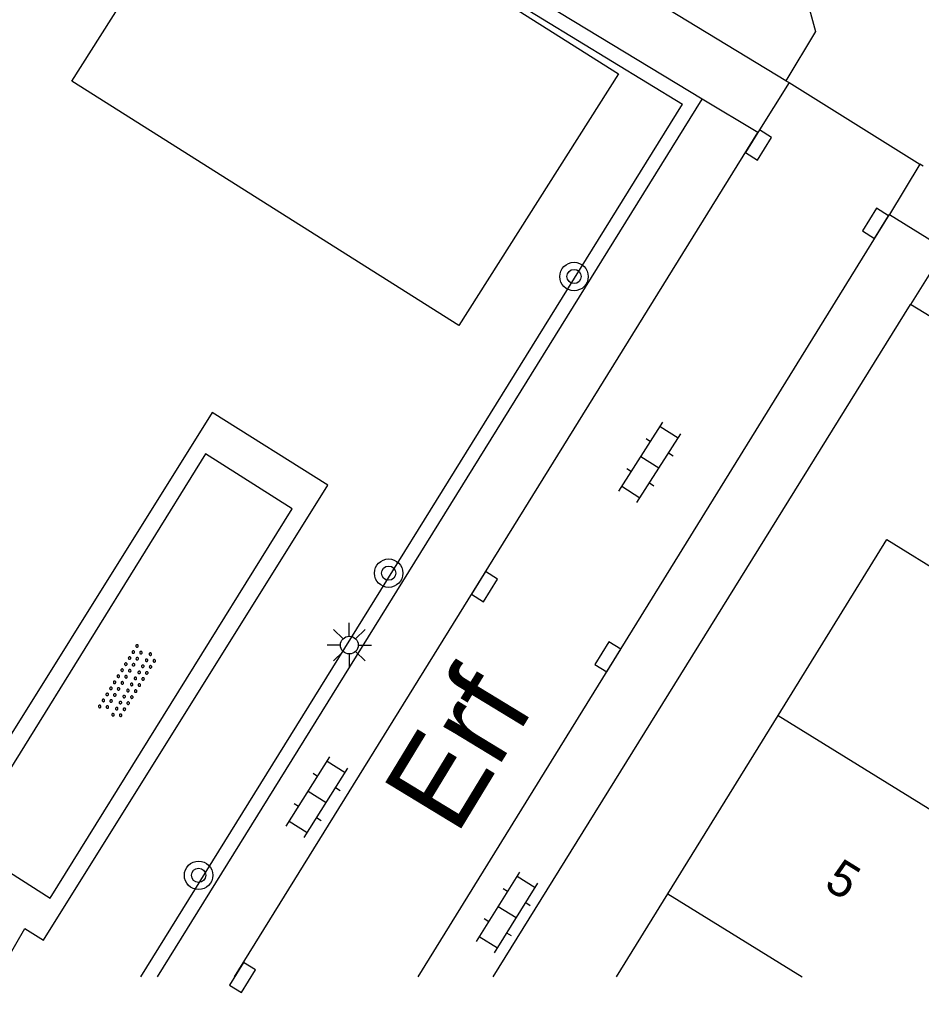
# Model space of a CAD drawing. Extents: x 136000 to 141014, y 402000 to 403500.
# Drawn here: x 137958.33 to 137983.69, y 401999.56 to 402026.92 of the extents above; entities that cross this region are included whole.
import ezdxf

# ---------------------------------------------------------------- set-up
doc = ezdxf.new("R2010")
doc.units = 0
for name, color, linetype in [('gg-anno-huisnummerreeks BGT', 7, 'Continuous'), ('gg-anno-openbare ruimte label', 7, 'Continuous'), ('gg-bbg-hoofdgebouw', 7, 'Continuous'), ('gg-bbg-tussenscheiding', 7, 'Continuous'), ('gg-knt-onverhard', 7, 'Continuous'), ('gg-knt-verharding', 7, 'Continuous'), ('gt-grn-groengrens', 7, 'Continuous'), ('gt-symb-boom', 7, 'Continuous'), ('gt-symb-klinker verharding', 7, 'Continuous'), ('gt-symb-kolk', 7, 'Continuous'), ('gt-symb-lichtmast', 7, 'Continuous'), ('gt-symb-overige verharding', 7, 'Continuous')]:
    doc.layers.add(name, color=color, linetype=linetype)

# ---------------------------------------------------------------- blocks, each defined once
blk = doc.blocks.new('gt0-KOLK')
at = {"layer": 'gt-symb-kolk'}
blk.add_lwpolyline([(0, 0), (0.375, 0), (0.375, 0.4), (-0.375, 0.4), (-0.375, 0), (0, 0)], dxfattribs=at)
blk = doc.blocks.new('gt0-KL1')
at = {"layer": 'gt-symb-klinker verharding'}
for p, q in [((-1.15, 0.3), (1.15, 0.3)), ((-1, -0.3), (-1, 0.3)), ((-0.5, 0.3), (-0.5, 0.45)), ((0, -0.3), (0, 0.3)), ((0.5, 0.3), (0.5, 0.45)), ((1, -0.3), (1, 0.3)), ((-1.15, -0.3), (1.15, -0.3)), ((-0.5, -0.45), (-0.5, -0.3)), ((0.5, -0.45), (0.5, -0.3))]:
    blk.add_line(p, q, dxfattribs=at)
blk = doc.blocks.new('gt0-OVH')
at = {"layer": 'gt-symb-overige verharding'}
for points in [[(-0.972, 0.298), (-0.967, 0.308), (-0.965, 0.319), (-0.966, 0.33), (-0.971, 0.34), (-0.978, 0.348), (-0.988, 0.353), (-0.999, 0.355), (-1.01, 0.354), (-1.02, 0.349), (-1.028, 0.342), (-1.033, 0.332), (-1.035, 0.321), (-1.034, 0.31), (-1.029, 0.3), (-1.022, 0.292), (-1.012, 0.287), (-1.001, 0.285), (-0.99, 0.286), (-0.98, 0.291)], [(-0.772, 0.298), (-0.767, 0.308), (-0.765, 0.319), (-0.766, 0.33), (-0.771, 0.34), (-0.778, 0.348), (-0.788, 0.353), (-0.799, 0.355), (-0.81, 0.354), (-0.82, 0.349), (-0.828, 0.342), (-0.833, 0.332), (-0.835, 0.321), (-0.834, 0.31), (-0.829, 0.3), (-0.822, 0.292), (-0.812, 0.287), (-0.801, 0.285), (-0.79, 0.286), (-0.78, 0.291)], [(-0.572, 0.298), (-0.567, 0.308), (-0.565, 0.319), (-0.566, 0.33), (-0.571, 0.34), (-0.578, 0.348), (-0.588, 0.353), (-0.599, 0.355), (-0.61, 0.354), (-0.62, 0.349), (-0.628, 0.342), (-0.633, 0.332), (-0.635, 0.321), (-0.634, 0.31), (-0.629, 0.3), (-0.622, 0.292), (-0.612, 0.287), (-0.601, 0.285), (-0.59, 0.286), (-0.58, 0.291)], [(-0.372, 0.298), (-0.367, 0.308), (-0.365, 0.319), (-0.366, 0.33), (-0.371, 0.34), (-0.378, 0.348), (-0.388, 0.353), (-0.399, 0.355), (-0.41, 0.354), (-0.42, 0.349), (-0.428, 0.342), (-0.433, 0.332), (-0.435, 0.321), (-0.434, 0.31), (-0.429, 0.3), (-0.422, 0.292), (-0.412, 0.287), (-0.401, 0.285), (-0.39, 0.286), (-0.38, 0.291)], [(-0.172, 0.298), (-0.167, 0.308), (-0.165, 0.319), (-0.166, 0.33), (-0.171, 0.34), (-0.178, 0.348), (-0.188, 0.353), (-0.199, 0.355), (-0.21, 0.354), (-0.22, 0.349), (-0.228, 0.342), (-0.233, 0.332), (-0.235, 0.321), (-0.234, 0.31), (-0.229, 0.3), (-0.222, 0.292), (-0.212, 0.287), (-0.201, 0.285), (-0.19, 0.286), (-0.18, 0.291)], [(0.028, 0.298), (0.033, 0.308), (0.035, 0.319), (0.034, 0.33), (0.029, 0.34), (0.022, 0.348), (0.012, 0.353), (0.001, 0.355), (-0.01, 0.354), (-0.02, 0.349), (-0.028, 0.342), (-0.033, 0.332), (-0.035, 0.321), (-0.034, 0.31), (-0.029, 0.3), (-0.022, 0.292), (-0.012, 0.287), (-0.001, 0.285), (0.01, 0.286), (0.02, 0.291)], [(0.228, 0.298), (0.233, 0.308), (0.235, 0.319), (0.234, 0.33), (0.229, 0.34), (0.222, 0.348), (0.212, 0.353), (0.201, 0.355), (0.19, 0.354), (0.18, 0.349), (0.172, 0.342), (0.167, 0.332), (0.165, 0.321), (0.166, 0.31), (0.171, 0.3), (0.178, 0.292), (0.188, 0.287), (0.199, 0.285), (0.21, 0.286), (0.22, 0.291)], [(0.428, 0.298), (0.433, 0.308), (0.435, 0.319), (0.434, 0.33), (0.429, 0.34), (0.422, 0.348), (0.412, 0.353), (0.401, 0.355), (0.39, 0.354), (0.38, 0.349), (0.372, 0.342), (0.367, 0.332), (0.365, 0.321), (0.366, 0.31), (0.371, 0.3), (0.378, 0.292), (0.388, 0.287), (0.399, 0.285), (0.41, 0.286), (0.42, 0.291)], [(0.628, 0.298), (0.633, 0.308), (0.635, 0.319), (0.634, 0.33), (0.629, 0.34), (0.622, 0.348), (0.612, 0.353), (0.601, 0.355), (0.59, 0.354), (0.58, 0.349), (0.572, 0.342), (0.567, 0.332), (0.565, 0.321), (0.566, 0.31), (0.571, 0.3), (0.578, 0.292), (0.588, 0.287), (0.599, 0.285), (0.61, 0.286), (0.62, 0.291)], [(0.828, 0.298), (0.833, 0.308), (0.835, 0.319), (0.834, 0.33), (0.829, 0.34), (0.822, 0.348), (0.812, 0.353), (0.801, 0.355), (0.79, 0.354), (0.78, 0.349), (0.772, 0.342), (0.767, 0.332), (0.765, 0.321), (0.766, 0.31), (0.771, 0.3), (0.778, 0.292), (0.788, 0.287), (0.799, 0.285), (0.81, 0.286), (0.82, 0.291)], [(1.028, 0.298), (1.033, 0.308), (1.035, 0.319), (1.034, 0.33), (1.029, 0.34), (1.022, 0.348), (1.012, 0.353), (1.001, 0.355), (0.99, 0.354), (0.98, 0.349), (0.972, 0.342), (0.967, 0.332), (0.965, 0.321), (0.966, 0.31), (0.971, 0.3), (0.978, 0.292), (0.988, 0.287), (0.999, 0.285), (1.01, 0.286), (1.02, 0.291)], [(-0.872, 0.106), (-0.867, 0.116), (-0.865, 0.126), (-0.866, 0.137), (-0.871, 0.147), (-0.878, 0.156), (-0.888, 0.161), (-0.899, 0.163), (-0.91, 0.162), (-0.92, 0.157), (-0.928, 0.15), (-0.933, 0.14), (-0.935, 0.129), (-0.934, 0.118), (-0.929, 0.108), (-0.922, 0.1), (-0.912, 0.095), (-0.901, 0.092), (-0.89, 0.094), (-0.88, 0.098)], [(-0.672, 0.106), (-0.667, 0.116), (-0.665, 0.126), (-0.666, 0.137), (-0.671, 0.147), (-0.678, 0.156), (-0.688, 0.161), (-0.699, 0.163), (-0.71, 0.162), (-0.72, 0.157), (-0.728, 0.15), (-0.733, 0.14), (-0.735, 0.129), (-0.734, 0.118), (-0.729, 0.108), (-0.722, 0.1), (-0.712, 0.095), (-0.701, 0.092), (-0.69, 0.094), (-0.68, 0.098)], [(-0.472, 0.106), (-0.467, 0.116), (-0.465, 0.126), (-0.466, 0.137), (-0.471, 0.147), (-0.478, 0.156), (-0.488, 0.161), (-0.499, 0.163), (-0.51, 0.162), (-0.52, 0.157), (-0.528, 0.15), (-0.533, 0.14), (-0.535, 0.129), (-0.534, 0.118), (-0.529, 0.108), (-0.522, 0.1), (-0.512, 0.095), (-0.501, 0.092), (-0.49, 0.094), (-0.48, 0.098)], [(-0.272, 0.106), (-0.267, 0.116), (-0.265, 0.126), (-0.266, 0.137), (-0.271, 0.147), (-0.278, 0.156), (-0.288, 0.161), (-0.299, 0.163), (-0.31, 0.162), (-0.32, 0.157), (-0.328, 0.15), (-0.333, 0.14), (-0.335, 0.129), (-0.334, 0.118), (-0.329, 0.108), (-0.322, 0.1), (-0.312, 0.095), (-0.301, 0.092), (-0.29, 0.094), (-0.28, 0.098)], [(-0.072, 0.106), (-0.067, 0.116), (-0.065, 0.126), (-0.066, 0.137), (-0.071, 0.147), (-0.078, 0.156), (-0.088, 0.161), (-0.099, 0.163), (-0.11, 0.162), (-0.12, 0.157), (-0.128, 0.15), (-0.133, 0.14), (-0.135, 0.129), (-0.134, 0.118), (-0.129, 0.108), (-0.122, 0.1), (-0.112, 0.095), (-0.101, 0.092), (-0.09, 0.094), (-0.08, 0.098)], [(0.128, 0.106), (0.133, 0.116), (0.135, 0.126), (0.134, 0.137), (0.129, 0.147), (0.122, 0.156), (0.112, 0.161), (0.101, 0.163), (0.09, 0.162), (0.08, 0.157), (0.072, 0.15), (0.067, 0.14), (0.065, 0.129), (0.066, 0.118), (0.071, 0.108), (0.078, 0.1), (0.088, 0.095), (0.099, 0.092), (0.11, 0.094), (0.12, 0.098)], [(0.328, 0.106), (0.333, 0.116), (0.335, 0.126), (0.334, 0.137), (0.329, 0.147), (0.322, 0.156), (0.312, 0.161), (0.301, 0.163), (0.29, 0.162), (0.28, 0.157), (0.272, 0.15), (0.267, 0.14), (0.265, 0.129), (0.266, 0.118), (0.271, 0.108), (0.278, 0.1), (0.288, 0.095), (0.299, 0.092), (0.31, 0.094), (0.32, 0.098)], [(0.528, 0.106), (0.533, 0.116), (0.535, 0.126), (0.534, 0.137), (0.529, 0.147), (0.522, 0.156), (0.512, 0.161), (0.501, 0.163), (0.49, 0.162), (0.48, 0.157), (0.472, 0.15), (0.467, 0.14), (0.465, 0.129), (0.466, 0.118), (0.471, 0.108), (0.478, 0.1), (0.488, 0.095), (0.499, 0.092), (0.51, 0.094), (0.52, 0.098)], [(0.728, 0.106), (0.733, 0.116), (0.735, 0.126), (0.734, 0.137), (0.729, 0.147), (0.722, 0.156), (0.712, 0.161), (0.701, 0.163), (0.69, 0.162), (0.68, 0.157), (0.672, 0.15), (0.667, 0.14), (0.665, 0.129), (0.666, 0.118), (0.671, 0.108), (0.678, 0.1), (0.688, 0.095), (0.699, 0.092), (0.71, 0.094), (0.72, 0.098)], [(0.928, 0.106), (0.933, 0.116), (0.935, 0.126), (0.934, 0.137), (0.929, 0.147), (0.922, 0.156), (0.912, 0.161), (0.901, 0.163), (0.89, 0.162), (0.88, 0.157), (0.872, 0.15), (0.867, 0.14), (0.865, 0.129), (0.866, 0.118), (0.871, 0.108), (0.878, 0.1), (0.888, 0.095), (0.899, 0.092), (0.91, 0.094), (0.92, 0.098)], [(-0.972, -0.142), (-0.967, -0.132), (-0.965, -0.121), (-0.966, -0.11), (-0.971, -0.1), (-0.978, -0.092), (-0.988, -0.087), (-0.999, -0.085), (-1.01, -0.086), (-1.02, -0.091), (-1.028, -0.098), (-1.033, -0.108), (-1.035, -0.119), (-1.034, -0.13), (-1.029, -0.14), (-1.022, -0.148), (-1.012, -0.153), (-1.001, -0.155), (-0.99, -0.154), (-0.98, -0.149)], [(-0.772, -0.142), (-0.767, -0.132), (-0.765, -0.121), (-0.766, -0.11), (-0.771, -0.1), (-0.778, -0.092), (-0.788, -0.087), (-0.799, -0.085), (-0.81, -0.086), (-0.82, -0.091), (-0.828, -0.098), (-0.833, -0.108), (-0.835, -0.119), (-0.834, -0.13), (-0.829, -0.14), (-0.822, -0.148), (-0.812, -0.153), (-0.801, -0.155), (-0.79, -0.154), (-0.78, -0.149)], [(-0.572, -0.142), (-0.567, -0.132), (-0.565, -0.121), (-0.566, -0.11), (-0.571, -0.1), (-0.578, -0.092), (-0.588, -0.087), (-0.599, -0.085), (-0.61, -0.086), (-0.62, -0.091), (-0.628, -0.098), (-0.633, -0.108), (-0.635, -0.119), (-0.634, -0.13), (-0.629, -0.14), (-0.622, -0.148), (-0.612, -0.153), (-0.601, -0.155), (-0.59, -0.154), (-0.58, -0.149)], [(-0.372, -0.142), (-0.367, -0.132), (-0.365, -0.121), (-0.366, -0.11), (-0.371, -0.1), (-0.378, -0.092), (-0.388, -0.087), (-0.399, -0.085), (-0.41, -0.086), (-0.42, -0.091), (-0.428, -0.098), (-0.433, -0.108), (-0.435, -0.119), (-0.434, -0.13), (-0.429, -0.14), (-0.422, -0.148), (-0.412, -0.153), (-0.401, -0.155), (-0.39, -0.154), (-0.38, -0.149)], [(-0.172, -0.142), (-0.167, -0.132), (-0.165, -0.121), (-0.166, -0.11), (-0.171, -0.1), (-0.178, -0.092), (-0.188, -0.087), (-0.199, -0.085), (-0.21, -0.086), (-0.22, -0.091), (-0.228, -0.098), (-0.233, -0.108), (-0.235, -0.119), (-0.234, -0.13), (-0.229, -0.14), (-0.222, -0.148), (-0.212, -0.153), (-0.201, -0.155), (-0.19, -0.154), (-0.18, -0.149)], [(0.028, -0.142), (0.033, -0.132), (0.035, -0.121), (0.034, -0.11), (0.029, -0.1), (0.022, -0.092), (0.012, -0.087), (0.001, -0.085), (-0.01, -0.086), (-0.02, -0.091), (-0.028, -0.098), (-0.033, -0.108), (-0.035, -0.119), (-0.034, -0.13), (-0.029, -0.14), (-0.022, -0.148), (-0.012, -0.153), (-0.001, -0.155), (0.01, -0.154), (0.02, -0.149)], [(0.228, -0.142), (0.233, -0.132), (0.235, -0.121), (0.234, -0.11), (0.229, -0.1), (0.222, -0.092), (0.212, -0.087), (0.201, -0.085), (0.19, -0.086), (0.18, -0.091), (0.172, -0.098), (0.167, -0.108), (0.165, -0.119), (0.166, -0.13), (0.171, -0.14), (0.178, -0.148), (0.188, -0.153), (0.199, -0.155), (0.21, -0.154), (0.22, -0.149)], [(0.428, -0.142), (0.433, -0.132), (0.435, -0.121), (0.434, -0.11), (0.429, -0.1), (0.422, -0.092), (0.412, -0.087), (0.401, -0.085), (0.39, -0.086), (0.38, -0.091), (0.372, -0.098), (0.367, -0.108), (0.365, -0.119), (0.366, -0.13), (0.371, -0.14), (0.378, -0.148), (0.388, -0.153), (0.399, -0.155), (0.41, -0.154), (0.42, -0.149)], [(0.628, -0.142), (0.633, -0.132), (0.635, -0.121), (0.634, -0.11), (0.629, -0.1), (0.622, -0.092), (0.612, -0.087), (0.601, -0.085), (0.59, -0.086), (0.58, -0.091), (0.572, -0.098), (0.567, -0.108), (0.565, -0.119), (0.566, -0.13), (0.571, -0.14), (0.578, -0.148), (0.588, -0.153), (0.599, -0.155), (0.61, -0.154), (0.62, -0.149)], [(0.828, -0.142), (0.833, -0.132), (0.835, -0.121), (0.834, -0.11), (0.829, -0.1), (0.822, -0.092), (0.812, -0.087), (0.801, -0.085), (0.79, -0.086), (0.78, -0.091), (0.772, -0.098), (0.767, -0.108), (0.765, -0.119), (0.766, -0.13), (0.771, -0.14), (0.778, -0.148), (0.788, -0.153), (0.799, -0.155), (0.81, -0.154), (0.82, -0.149)], [(1.028, -0.142), (1.033, -0.132), (1.035, -0.121), (1.034, -0.11), (1.029, -0.1), (1.022, -0.092), (1.012, -0.087), (1.001, -0.085), (0.99, -0.086), (0.98, -0.091), (0.972, -0.098), (0.967, -0.108), (0.965, -0.119), (0.966, -0.13), (0.971, -0.14), (0.978, -0.148), (0.988, -0.153), (0.999, -0.155), (1.01, -0.154), (1.02, -0.149)], [(-0.872, -0.334), (-0.867, -0.324), (-0.865, -0.314), (-0.866, -0.303), (-0.871, -0.293), (-0.878, -0.284), (-0.888, -0.279), (-0.899, -0.277), (-0.91, -0.278), (-0.92, -0.283), (-0.928, -0.29), (-0.933, -0.3), (-0.935, -0.311), (-0.934, -0.322), (-0.929, -0.332), (-0.922, -0.34), (-0.912, -0.345), (-0.901, -0.348), (-0.89, -0.346), (-0.88, -0.342)], [(-0.672, -0.334), (-0.667, -0.324), (-0.665, -0.314), (-0.666, -0.303), (-0.671, -0.293), (-0.678, -0.284), (-0.688, -0.279), (-0.699, -0.277), (-0.71, -0.278), (-0.72, -0.283), (-0.728, -0.29), (-0.733, -0.3), (-0.735, -0.311), (-0.734, -0.322), (-0.729, -0.332), (-0.722, -0.34), (-0.712, -0.345), (-0.701, -0.348), (-0.69, -0.346), (-0.68, -0.342)], [(-0.472, -0.334), (-0.467, -0.324), (-0.465, -0.314), (-0.466, -0.303), (-0.471, -0.293), (-0.478, -0.284), (-0.488, -0.279), (-0.499, -0.277), (-0.51, -0.278), (-0.52, -0.283), (-0.528, -0.29), (-0.533, -0.3), (-0.535, -0.311), (-0.534, -0.322), (-0.529, -0.332), (-0.522, -0.34), (-0.512, -0.345), (-0.501, -0.348), (-0.49, -0.346), (-0.48, -0.342)], [(-0.272, -0.334), (-0.267, -0.324), (-0.265, -0.314), (-0.266, -0.303), (-0.271, -0.293), (-0.278, -0.284), (-0.288, -0.279), (-0.299, -0.277), (-0.31, -0.278), (-0.32, -0.283), (-0.328, -0.29), (-0.333, -0.3), (-0.335, -0.311), (-0.334, -0.322), (-0.329, -0.332), (-0.322, -0.34), (-0.312, -0.345), (-0.301, -0.348), (-0.29, -0.346), (-0.28, -0.342)], [(-0.072, -0.334), (-0.067, -0.324), (-0.065, -0.314), (-0.066, -0.303), (-0.071, -0.293), (-0.078, -0.284), (-0.088, -0.279), (-0.099, -0.277), (-0.11, -0.278), (-0.12, -0.283), (-0.128, -0.29), (-0.133, -0.3), (-0.135, -0.311), (-0.134, -0.322), (-0.129, -0.332), (-0.122, -0.34), (-0.112, -0.345), (-0.101, -0.348), (-0.09, -0.346), (-0.08, -0.342)], [(0.128, -0.334), (0.133, -0.324), (0.135, -0.314), (0.134, -0.303), (0.129, -0.293), (0.122, -0.284), (0.112, -0.279), (0.101, -0.277), (0.09, -0.278), (0.08, -0.283), (0.072, -0.29), (0.067, -0.3), (0.065, -0.311), (0.066, -0.322), (0.071, -0.332), (0.078, -0.34), (0.088, -0.345), (0.099, -0.348), (0.11, -0.346), (0.12, -0.342)], [(0.328, -0.334), (0.333, -0.324), (0.335, -0.314), (0.334, -0.303), (0.329, -0.293), (0.322, -0.284), (0.312, -0.279), (0.301, -0.277), (0.29, -0.278), (0.28, -0.283), (0.272, -0.29), (0.267, -0.3), (0.265, -0.311), (0.266, -0.322), (0.271, -0.332), (0.278, -0.34), (0.288, -0.345), (0.299, -0.348), (0.31, -0.346), (0.32, -0.342)], [(0.528, -0.334), (0.533, -0.324), (0.535, -0.314), (0.534, -0.303), (0.529, -0.293), (0.522, -0.284), (0.512, -0.279), (0.501, -0.277), (0.49, -0.278), (0.48, -0.283), (0.472, -0.29), (0.467, -0.3), (0.465, -0.311), (0.466, -0.322), (0.471, -0.332), (0.478, -0.34), (0.488, -0.345), (0.499, -0.348), (0.51, -0.346), (0.52, -0.342)], [(0.728, -0.334), (0.733, -0.324), (0.735, -0.314), (0.734, -0.303), (0.729, -0.293), (0.722, -0.284), (0.712, -0.279), (0.701, -0.277), (0.69, -0.278), (0.68, -0.283), (0.672, -0.29), (0.667, -0.3), (0.665, -0.311), (0.666, -0.322), (0.671, -0.332), (0.678, -0.34), (0.688, -0.345), (0.699, -0.348), (0.71, -0.346), (0.72, -0.342)], [(0.928, -0.334), (0.933, -0.324), (0.935, -0.314), (0.934, -0.303), (0.929, -0.293), (0.922, -0.284), (0.912, -0.279), (0.901, -0.277), (0.89, -0.278), (0.88, -0.283), (0.872, -0.29), (0.867, -0.3), (0.865, -0.311), (0.866, -0.322), (0.871, -0.332), (0.878, -0.34), (0.888, -0.345), (0.899, -0.348), (0.91, -0.346), (0.92, -0.342)]]:
    blk.add_lwpolyline(points, close=True, dxfattribs=at)
blk = doc.blocks.new('gt0-LMAST')
at = {"layer": 'gt-symb-lichtmast'}
for p, q in [((-0.005, 0.246), (-0.005, 0.621)), ((-0.182, 0.173), (-0.447, 0.438)), ((0.172, 0.173), (0.437, 0.438)), ((-0.255, -0.004), (-0.63, -0.004)), ((-0.182, -0.181), (-0.447, -0.446)), ((-0.005, -0.254), (-0.005, -0.629)), ((0.437, -0.446), (0.172, -0.181)), ((0.245, -0.004), (0.62, -0.004))]:
    blk.add_line(p, q, dxfattribs=at)
blk.add_circle((-0.005, -0.004), 0.25, dxfattribs=at)
blk = doc.blocks.new('gt0-BOOM')
at = {"layer": 'gt-symb-boom'}
for radius in [0.4, 0.2]:
    blk.add_circle((0, 0), radius, dxfattribs=at)

msp = doc.modelspace()

# ---------------------------------------------------------------- linework, layer by layer
at = {"layer": 'gg-bbg-hoofdgebouw'}
for p, q in [((137976.556, 402002.332), (137979.657, 402007.348)), ((137975.114, 402000), (137976.556, 402002.332))]:
    msp.add_line(p, q, dxfattribs=at)
msp.add_lwpolyline([(137979.657, 402007.348), (137982.717, 402012.299), (137984.41, 402011.246), (137984.455, 402011.318)], dxfattribs=at)
at = {"layer": 'gg-bbg-tussenscheiding'}
for p, q in [((137979.657, 402007.348), (137987.598, 402002.45)), ((137976.556, 402002.332), (137980.337, 402000))]:
    msp.add_line(p, q, dxfattribs=at)
at = {"layer": 'gg-knt-onverhard'}
msp.add_lwpolyline([(137964.289, 402032.268), (137975.168, 402025.392), (137970.682, 402018.312), (137959.803, 402025.187), (137964.289, 402032.268)], dxfattribs=at)
at = {"layer": 'gg-knt-verharding'}
for p, q in [((137977.526, 402024.676), (137960.071, 402035.275)), ((137979.973, 402025.146), (137979.092, 402023.746)), ((137979.873, 402025.191), (137979.973, 402025.146)), ((137979.973, 402025.146), (137983.648, 402022.852)), ((137962.212, 402000), (137977.526, 402024.676)), ((137979.092, 402023.746), (137977.526, 402024.676)), ((137964.374, 402000), (137979.092, 402023.746)), ((137983.648, 402022.852), (137982.793, 402021.44)), ((137983.737, 402022.793), (137983.648, 402022.852)), ((137969.543, 402000), (137982.793, 402021.44)), ((137982.793, 402021.44), (137984.35, 402020.466)), ((137984.35, 402020.466), (137983.381, 402018.905)), ((137971.65, 402000), (137983.381, 402018.905))]:
    msp.add_line(p, q, dxfattribs=at)
for points in [[(137979.873, 402025.191), (137953.053, 402041.473), (137954.425, 402043.666)], [(137979.654, 402030.477), (137980.709, 402026.583), (137979.873, 402025.191)], [(137957.711, 402000.04), (137958.481, 402001.359), (137959.002, 402001.032), (137966.998, 402013.823), (137963.746, 402015.87), (137955.762, 402003.099), (137956.489, 402002.643)], [(137956.766, 402003.757), (137959.194, 402002.214), (137965.995, 402013.161), (137963.563, 402014.703), (137956.766, 402003.757)]]:
    msp.add_lwpolyline(points, dxfattribs=at)
at = {"layer": 'gt-grn-groengrens'}
for p, q in [((137964.289, 402032.268), (137976.973, 402024.544)), ((137961.741, 402000), (137976.973, 402024.544)), ((137987.57, 402016.325), (137983.381, 402018.905))]:
    msp.add_line(p, q, dxfattribs=at)

# ---------------------------------------------------------------- block references
at = {"layer": 'gt-symb-boom'}
for p in [(137973.922, 402019.692), (137968.71, 402011.35), (137963.365, 402002.854)]:
    msp.add_blockref('gt0-BOOM', p, dxfattribs=at)
at = {"layer": 'gt-symb-klinker verharding'}
for p, rotation in [((137976.057, 402014.465), 57.454106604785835), ((137966.697, 402005.051), 57.70905164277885), ((137972.043, 402001.813), 57.9946167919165)]:
    msp.add_blockref('gt0-KL1', p, dxfattribs=dict(at, rotation=rotation))
at = {"layer": 'gt-symb-kolk'}
for p, rotation in [((137979.278, 402023.287), 58.20108717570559), ((137982.569, 402021.085), 58.20108717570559), ((137971.575, 402010.866), 58.20108717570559), ((137975.04, 402008.893), 58.20108717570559), ((137964.428, 402000.087), -121.72006011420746)]:
    msp.add_blockref('gt0-KOLK', p, dxfattribs=dict(at, rotation=rotation))
at = {"layer": 'gt-symb-lichtmast'}
msp.add_blockref('gt0-LMAST', (137967.608, 402009.333), dxfattribs=at)
at = {"layer": 'gt-symb-overige verharding', "rotation": 58.32868147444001}
msp.add_blockref('gt0-OVH', (137961.381, 402008.284), dxfattribs=at)

# ---------------------------------------------------------------- texts
at = {"layer": 'gg-anno-huisnummerreeks BGT'}
msp.add_text('5', height=1, rotation=328.3, dxfattribs=at).set_placement((137980.914, 402002.514))
at = {"layer": 'gg-anno-openbare ruimte label'}
msp.add_text('Erf', height=2.5, rotation=58.7, dxfattribs=at).set_placement((137970.609, 402003.938))

doc.saveas('drawing.dxf')
